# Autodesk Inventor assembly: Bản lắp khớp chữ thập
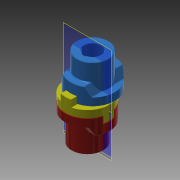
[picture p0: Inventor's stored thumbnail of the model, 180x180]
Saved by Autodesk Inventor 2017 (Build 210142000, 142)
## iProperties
Created: 2011-05
Part Number: Bản lắp khớp chữ thập
Document SubType Name: Assembly
Designer: Administrator
Author: Administrator
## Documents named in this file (4)
- F:\Use Autodesk Inventor\Oldham Coupling\Oldham Coupling.iam
- F:\Use Autodesk Inventor\Oldham Coupling\Flange - 1.ipt
- F:\Use Autodesk Inventor\Oldham Coupling\Flange - 2.ipt
- F:\Use Autodesk Inventor\Oldham Coupling\Dish.ipt
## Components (3 placed, 3 different names)
1. Flange - 1:1 — Mate:1, Mate:7, Mate:8, Angle:2, Mate:12, Angle:3
2. Dish:1 — Mate:1, Angle:1, Angle:2, Mate:11, Mate:12, Mate:13
3. Flange - 2:1 — Mate:9, Mate:10, Angle:1, Mate:11, Mate:13
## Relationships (11: Mate 8, Angle 3)
- Mate:1: Flange - 1:1 ↔ Dish:1
- Mate:7: Flange - 1:1
- Mate:8: Flange - 1:1
- Mate:9: Flange - 2:1
- Mate:10: Flange - 2:1
- Angle:1: Dish:1 ↔ Flange - 2:1
- Angle:2: Flange - 1:1 ↔ Dish:1
- Mate:11: Dish:1 ↔ Flange - 2:1
- Mate:12: Flange - 1:1 ↔ Dish:1
- Mate:13: Dish:1 ↔ Flange - 2:1
- Angle:3: Flange - 1:1
